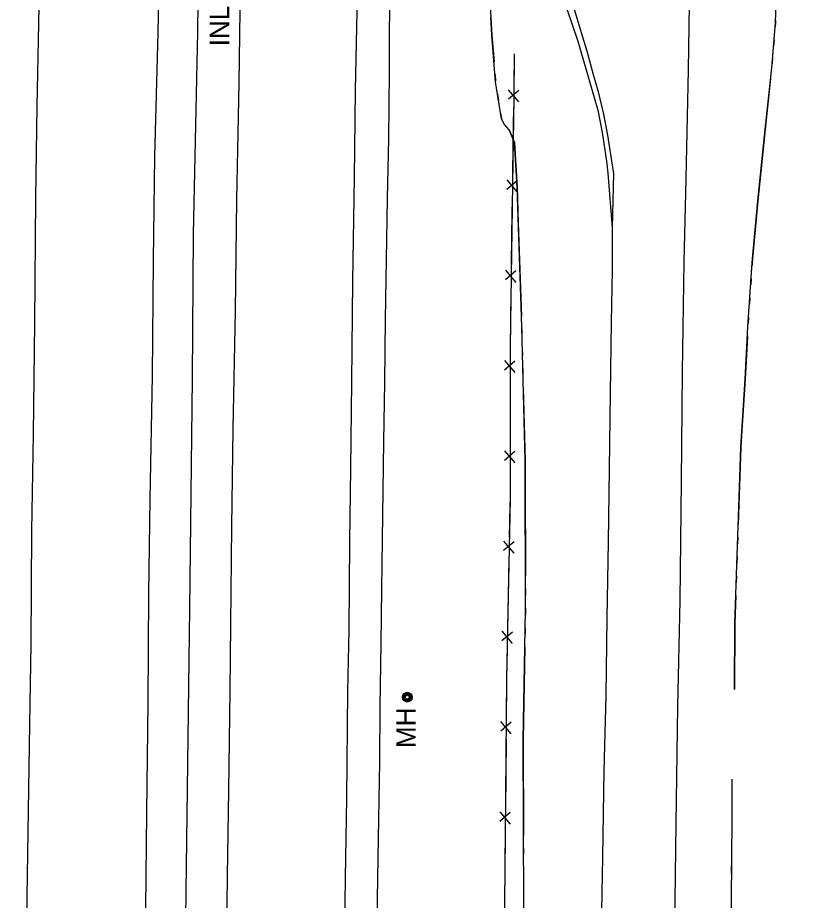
# Model space of a CAD drawing. Extents: x 591954 to 597000, y 198576 to 213500.
# Drawn here: x 594027.3 to 594269, y 205561.3 to 205833.7 of the extents above; entities that cross this region are included whole.
import ezdxf

# ---------------------------------------------------------------- set-up
doc = ezdxf.new("R2010")
doc.units = 0
for name, color, linetype in [('Level 11', 7, 'Continuous'), ('Level 15', 7, 'Continuous'), ('Level 16', 7, 'Continuous'), ('Level 19', 7, 'Continuous')]:
    doc.layers.add(name, color=color, linetype=linetype)

msp = doc.modelspace()

# ---------------------------------------------------------------- linework, layer by layer
at = {"layer": 'Level 11'}
for points in [[(594071.22, 205860.69), (594070.57, 205829.04), (594069.61, 205790.97), (594069.19, 205758.83), (594068.81, 205723.22), (594068.11, 205685.16), (594067.74, 205656.06), (594067.48, 205622.39), (594067.08, 205588.31), (594066.72, 205549.18), (594066.3, 205514.76), (594065.7, 205484.05), (594065.54, 205454.85), (594065.28, 205421.18), (594064.93, 205388.3), (594064.33, 205351.14), (594063.8, 205305.89), (594063.32, 205268.34), (594063.21, 205228.02), (594062.65, 205187.89), (594061.98, 205150.08), (594061.98, 205112.8)], [(594142.59, 205853.5), (594142.02, 205830.71), (594142.03, 205816.96), (594141.81, 205796.42), (594141.44, 205777.87), (594141.08, 205759.09), (594140.74, 205740.67), (594140.55, 205721.11), (594140.3, 205702.92), (594139.98, 205680.25), (594139.64, 205657.48), (594139.4, 205640.47), (594139.13, 205621.11), (594138.99, 205604.1), (594138.78, 205586.47), (594138.42, 205568.31), (594138.16, 205548.23), (594137.98, 205528.93), (594137.73, 205507.08), (594137.29, 205480.68), (594136.91, 205457.32), (594136.99, 205448.36), (594136.91, 205440.87), (594137.89, 205440.79)], [(594234.88, 205851.37), (594234.34, 205817.6), (594233.58, 205784), (594233.02, 205758.34), (594232.48, 205724.47), (594232.12, 205690.64), (594231.71, 205653.92), (594231.09, 205621.21), (594230.52, 205584.98), (594230.09, 205553.36), (594229.7, 205523.28), (594229.04, 205488.21), (594228.47, 205459.81), (594227.82, 205428.49), (594227.4, 205390.41), (594226.61, 205356.6), (594226.08, 205321.99), (594225.23, 205292.59), (594224.83, 205260.38), (594224.14, 205232.18), (594223.94, 205194.81)], [(594034, 205842.33), (594033.28, 205806.43), (594032.86, 205777.99), (594032.56, 205739.53), (594032.16, 205705.16), (594031.63, 205675.36), (594031.43, 205640.48), (594030.98, 205615.71), (594029.63, 205529.08), (594029.38, 205492.27), (594029.11, 205453.08), (594028.51, 205412.47), (594028.15, 205392.44), (594027.94, 205356.69), (594027.31, 205320.7), (594027.23, 205294.59), (594026.37, 205216.35), (594025.95, 205182.33), (594025.49, 205139.55), (594024.98, 205101.82), (594024.63, 205068.11), (594024.13, 205026.24), (594023.86, 205005.44), (594023.86, 205000.64)], [(594096.03, 205843.42), (594095.57, 205813.49), (594094.94, 205777.64), (594094.43, 205743.28), (594093.76, 205706.8), (594093.34, 205676.69), (594093.02, 205646.51), (594092.79, 205625.96), (594092.42, 205595.39), (594092.04, 205568.93), (594091.67, 205542.37)], [(594197.45, 205841.92), (594200.36, 205832.23), (594203.1, 205823.12), (594205.04, 205816.23), (594206.46, 205811.21), (594208.24, 205803.99), (594209.38, 205797.51), (594210.7, 205789.55), (594211.25, 205785.62), (594210.91, 205768.84), (594210.86, 205755.82), (594210.54, 205739.76), (594210.23, 205717.87), (594209.98, 205694.46), (594209.63, 205671.98), (594209.19, 205648.43), (594208.88, 205624.52), (594208.33, 205601.31), (594207.85, 205574.81), (594207.35, 205546.75)], [(594132.16, 205840.58), (594131.52, 205811.36), (594131.18, 205784.27), (594130.72, 205752.54), (594130.37, 205721.3), (594130.08, 205694.61), (594129.79, 205672.03), (594129.52, 205644.78), (594129.21, 205625.9), (594128.85, 205592.75), (594128.45, 205568.25), (594127.98, 205536.73)], [(594195.14, 205840.97), (594196.96, 205836.18), (594200.22, 205826.42), (594203, 205816.93), (594206.48, 205805.16), (594207.77, 205798.26), (594209.15, 205789.46), (594209.52, 205785.71), (594210.91, 205768.84)]]:
    msp.add_lwpolyline(points, dxfattribs=at)
at = {"layer": 'Level 15'}
for p, q in [((594178.78, 205811.49), (594181.98, 205807.74)), ((594182.01, 205811.29), (594178.82, 205808.52)), ((594178.33, 205783.64), (594181.51, 205779.87)), ((594181.56, 205783.42), (594178.35, 205780.67)), ((594177.94, 205755.78), (594181.12, 205752.02)), ((594181.17, 205755.57), (594177.96, 205752.81)), ((594177.61, 205727.9), (594180.85, 205724.18)), ((594180.85, 205727.73), (594177.68, 205724.93)), ((594177.61, 205700.04), (594180.85, 205696.32)), ((594180.85, 205699.87), (594177.68, 205697.07)), ((594177.36, 205672.21), (594180.53, 205668.43)), ((594180.6, 205671.98), (594177.37, 205669.25)), ((594176.83, 205644.36), (594179.99, 205640.58)), ((594180.06, 205644.13), (594176.84, 205641.39)), ((594176.43, 205616.48), (594179.63, 205612.74)), ((594179.66, 205616.29), (594176.47, 205613.52)), ((594176.18, 205588.62), (594179.38, 205584.88)), ((594179.42, 205588.43), (594176.22, 205585.66))]:
    msp.add_line(p, q, dxfattribs=at)
for points in [[(594072.86, 205003.04), (594073.2, 205064.46), (594074.41, 205140.34), (594075.14, 205210.39), (594075.96, 205266.76), (594076.67, 205340.1), (594077.36, 205404.18), (594077.85, 205447.33), (594078.79, 205524.08), (594079.66, 205587.86), (594080.46, 205651.29), (594081.27, 205722.38), (594081.65, 205766.88), (594082.93, 205829.36), (594083.82, 205902.01), (594085.44, 205986.78)], [(594180.58, 205822.59), (594180.49, 205809.11), (594180.05, 205782.42), (594179.35, 205732.43), (594179.35, 205685.27), (594178.29, 205629.9), (594177.75, 205569.68), (594176.87, 205508.31), (594176.57, 205446.62), (594175.9, 205393.15), (594174.88, 205337.75), (594174.16, 205284.32), (594173.94, 205230.52), (594172.73, 205180.21), (594173.23, 205131.76), (594172.34, 205085.95), (594172.03, 205045.74), (594171.66, 205006.71)], [(594180.58, 205822.59), (594180.52, 205812.63)], [(594180.44, 205806.05), (594180.25, 205794.73)], [(594180.25, 205794.73), (594180.09, 205784.77)], [(594179.99, 205778.19), (594179.83, 205766.87)], [(594179.83, 205766.87), (594179.69, 205756.92)], [(594179.6, 205750.33), (594179.44, 205739.01)], [(594179.44, 205739.01), (594179.35, 205732.43), (594179.35, 205729.06)], [(594179.35, 205722.48), (594179.35, 205711.15)], [(594179.35, 205711.15), (594179.35, 205701.2)], [(594179.35, 205694.62), (594179.35, 205685.27), (594179.31, 205683.3)], [(594179.31, 205683.3), (594179.12, 205673.34)], [(594179, 205666.76), (594178.78, 205655.44)], [(594178.78, 205655.44), (594178.59, 205645.49)], [(594178.46, 205638.9), (594178.29, 205629.9), (594178.27, 205627.58)], [(594178.27, 205627.58), (594178.18, 205617.63)], [(594178.12, 205611.05), (594178.02, 205599.73)], [(594178.02, 205599.73), (594177.93, 205589.77)], [(594177.87, 205583.19), (594177.77, 205571.87)], [(594177.77, 205571.87), (594177.75, 205569.68), (594177.64, 205561.91)]]:
    msp.add_lwpolyline(points, dxfattribs=at)
at = {"layer": 'Level 16'}
for centre, radius in [((594147.63, 205624.04), 1.5), ((594147.63, 205624.04), 1.22), ((594147.63, 205624.02), 0.968), ((594147.6, 205624.02), 0.605)]:
    msp.add_circle(centre, radius, dxfattribs=at)
at = {"layer": 'Level 19'}
for points in [[(594248.65, 205626.4), (594248.7, 205646.79), (594249.76, 205676.71), (594250.56, 205701.16), (594251.94, 205722.2), (594252.77, 205738.3), (594254.12, 205758.19), (594255.8, 205777.21), (594257.94, 205797.27), (594260.13, 205818.26), (594261.28, 205832.17), (594261.57, 205841.59), (594261.78, 205853.68), (594261.64, 205869.86), (594260.08, 205886.61), (594259.05, 205909.41), (594257.64, 205923.63), (594257.18, 205937.51), (594256.52, 205950.23), (594255.9, 205963.94)], [(594173.7, 205842), (594173.4, 205839.25), (594173.22, 205836.93), (594173.41, 205833.87), (594173.75, 205828.36), (594174.39, 205820.14)], [(594174.08, 205210.67), (594175.08, 205231.16), (594176.9, 205257.78), (594178.03, 205288), (594179.23, 205319.98), (594179.35, 205352.76), (594180.26, 205384.77), (594181.18, 205418.53), (594181.95, 205445.38), (594182.23, 205477.74), (594182.17, 205511.27), (594183.55, 205559.12), (594183.41, 205611.01), (594184.16, 205650.85), (594183.96, 205696.98), (594182.93, 205738.39), (594181.5, 205781.3), (594180.69, 205795.19), (594179.09, 205799.13), (594177.6, 205800.76), (594176.72, 205802.47), (594174.88, 205813.96), (594173.75, 205828.36), (594173.41, 205833.87)], [(594261.3, 205832.91), (594261.28, 205832.17), (594261.17, 205830.91)], [(594260.84, 205826.93), (594260.68, 205824.93)], [(594260.35, 205820.95), (594260.18, 205818.96)], [(594174.7, 205816.15), (594174.86, 205814.16)], [(594259.78, 205814.98), (594257.94, 205797.27), (594256.75, 205786.13)], [(594175.48, 205810.21), (594175.8, 205808.23)], [(594176.43, 205804.28), (594176.72, 205802.47), (594176.8, 205802.33)], [(594179.1, 205799.1), (594180.69, 205795.19), (594181.5, 205781.3), (594181.86, 205770.44)], [(594256.75, 205786.13), (594255.8, 205777.21), (594254.12, 205758.19), (594254.06, 205757.26)], [(594181.86, 205770.44), (594182.83, 205741.46)], [(594253.79, 205753.27), (594253.65, 205751.27)], [(594253.38, 205747.28), (594253.25, 205745.29)], [(594252.98, 205741.3), (594252.84, 205739.3)], [(594182.95, 205737.46), (594183, 205735.46)], [(594252.62, 205735.31), (594251.94, 205722.2), (594250.9, 205706.36)], [(594183.1, 205731.46), (594183.15, 205729.46)], [(594183.25, 205725.46), (594183.3, 205723.46)], [(594183.4, 205719.46), (594183.96, 205696.98), (594183.98, 205690.47)], [(594250.9, 205706.36), (594250.56, 205701.16), (594249.78, 205677.38)], [(594183.98, 205690.47), (594184.11, 205661.47)], [(594249.64, 205673.39), (594249.57, 205671.39)], [(594249.43, 205667.39), (594249.36, 205665.39)], [(594249.22, 205661.39), (594249.15, 205659.4)], [(594184.13, 205657.47), (594184.14, 205655.47)], [(594249.01, 205655.4), (594248.7, 205646.79), (594248.65, 205626.4)], [(594184.16, 205651.47), (594184.16, 205650.85), (594184.13, 205649.47)], [(594184.06, 205645.47), (594184.02, 205643.47)], [(594183.95, 205639.47), (594183.41, 205611.01), (594183.42, 205610.48)], [(594183.42, 205610.48), (594183.49, 205581.48)], [(594247.83, 205598.69), (594247.77, 205586.41), (594247.67, 205574.13), (594247.58, 205560.91), (594247.65, 205548.05), (594247.92, 205537.27), (594248.17, 205528.53), (594248.41, 205520.91), (594249.18, 205512.01), (594250.3, 205504.04), (594251.23, 205495.54), (594251.76, 205489.54), (594252.91, 205481.78), (594254.63, 205472.59), (594255.4, 205463.73), (594256.68, 205456.96), (594257.12, 205452.18), (594258.07, 205445.69), (594259.43, 205442.15), (594263.84, 205438.43), (594268.97, 205435.21)], [(594247.83, 205598.69), (594247.77, 205586.41), (594247.67, 205574.13), (594247.64, 205569.7)], [(594183.5, 205577.48), (594183.51, 205575.48)], [(594183.52, 205571.48), (594183.52, 205569.48)], [(594183.53, 205565.48), (594183.54, 205563.48)], [(594247.61, 205565.7), (594247.6, 205563.7)]]:
    msp.add_lwpolyline(points, dxfattribs=at)

# ---------------------------------------------------------------- texts
at = {"layer": 'Level 15'}
msp.add_text('INL', height=6, rotation=90, dxfattribs=at).set_placement((594092.65, 205824.89))
at = {"layer": 'Level 16'}
msp.add_text('MH', height=6, rotation=90, dxfattribs=at).set_placement((594150.21, 205608.34))

doc.saveas('drawing.dxf')
